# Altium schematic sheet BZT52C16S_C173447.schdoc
size 127 x 101 mm
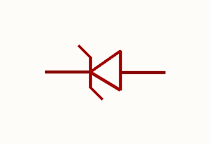
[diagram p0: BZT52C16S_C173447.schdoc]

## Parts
D?  bzt52c16s_c173447  [SOD-323_L1.8-W1.3-LS2.5-RD]  (value not drawn)

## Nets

Not connected (* = marked no-connect by the designer): D? 1 2

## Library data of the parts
D? = bzt52c16s_c173447: 二极管配置:1个独立式;稳压值(标称值):16V;稳压值(范围值):15.3V~17.1V;耗散功率(Pd):200mW;; Manufacturer: MDD(辰达半导体); AddInBom: yes; ModelId: db63db13d9e342eb939127d413d6200b; ModelTransform: 104.3305,51.181,0,0,0,0,0,-0.004,0; Diode Configuration: 1个独立式; Zener Voltage(Nom): 16V; Reverse Leakage Current (Ir): 100nA@12V; Pd - Power Dissipation: 200mW; Impedance(Zzt): 40Ω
